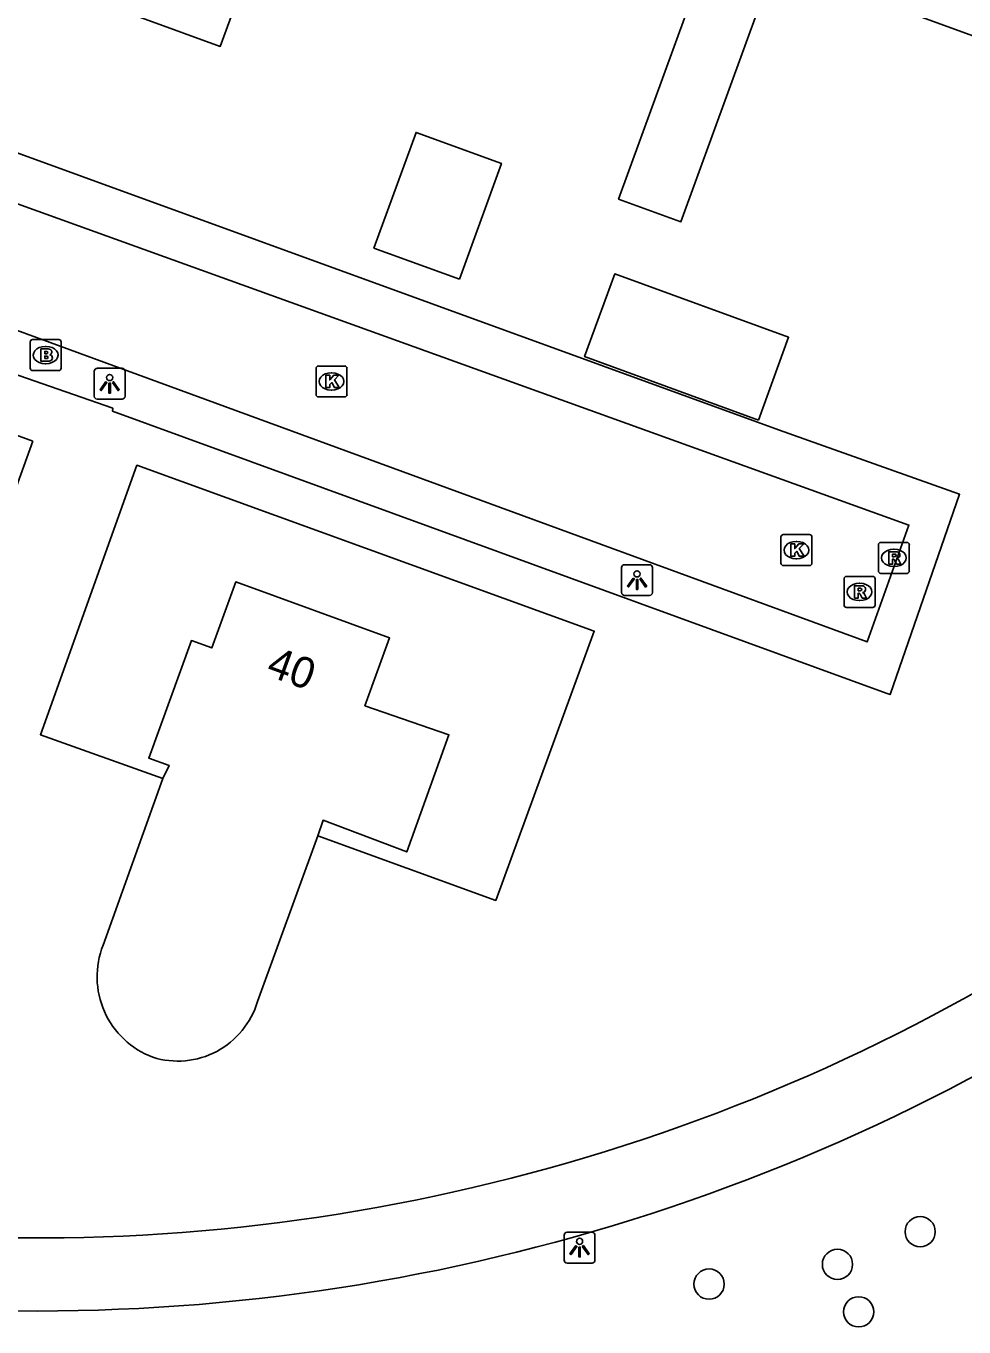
# Model space of a CAD drawing. Extents: x 155275 to 156263, y 382654 to 383635.
# Drawn here: x 155986.87 to 156017.19, y 382833.06 to 382875.11 of the extents above; entities that cross this region are included whole.
import ezdxf

# ---------------------------------------------------------------- set-up
doc = ezdxf.new("R2010")
doc.units = 0
for name, color, linetype in [('IMGEO_Boom', 7, 'Continuous'), ('IMGEO_Brandkraan', 7, 'Continuous'), ('IMGEO_Kolk', 7, 'Continuous'), ('IMGEO_Lichtpunt', 7, 'Continuous'), ('IMGEO_Pand', 7, 'Continuous'), ('IMGEO_Pand_nummerreeks', 7, 'Continuous'), ('IMGEO_Pand_overbouw', 7, 'Continuous'), ('IMGEO_Rijbaan_lokaal_open', 7, 'Continuous'), ('IMGEO_Rioolput', 7, 'Continuous'), ('IMGEO_Voetpad_open', 7, 'Continuous')]:
    doc.layers.add(name, color=color, linetype=linetype)

msp = doc.modelspace()

# ---------------------------------------------------------------- linework, layer by layer
at = {"layer": 'IMGEO_Boom'}
for centre in [(156015.775, 382836.141), (156013.102, 382835.085), (156008.951, 382834.447), (156013.787, 382833.551)]:
    msp.add_circle(centre, 0.489, dxfattribs=at)
at = {"layer": 'IMGEO_Brandkraan'}
for p, q in [((155987.002, 382864.048), (155987.002, 382864.9)), ((155987.077, 382864.974), (155987.929, 382864.974)), ((155988.003, 382864.9), (155988.003, 382864.048)), ((155987.49, 382864.754), (155987.515, 382864.754)), ((155987.929, 382863.974), (155987.077, 382863.974)), ((155987.513, 382864.194), (155987.488, 382864.194))]:
    msp.add_line(p, q, dxfattribs=at)
for points in [[(155987.002, 382864.048), (155987.002, 382864.9)], [(155987.077, 382864.974), (155987.929, 382864.974)], [(155988.003, 382864.9), (155988.003, 382864.048)], [(155987.35, 382864.674), (155987.35, 382864.274), (155987.563, 382864.274)], [(155987.581, 382864.674), (155987.35, 382864.674)], [(155987.529, 382864.593), (155987.475, 382864.593), (155987.475, 382864.517)], [(155987.475, 382864.517), (155987.528, 382864.517)], [(155987.537, 382864.441), (155987.475, 382864.441), (155987.475, 382864.36)], [(155987.475, 382864.36), (155987.537, 382864.36)], [(155987.929, 382863.974), (155987.077, 382863.974)]]:
    msp.add_lwpolyline(points, dxfattribs=at)
for centre, radius, start, end in [((155987.079, 382864.898), 0.0765, 91.552, 178.448), ((155987.079, 382864.898), 0.0765, 91.552, 178.448), ((155987.927, 382864.898), 0.0765, 1.552, 88.448), ((155987.927, 382864.898), 0.0765, 1.552, 88.448), ((155987.53, 382864.555), 0.0379, 267.8285, 90.9355), ((155987.538, 382864.4), 0.0404, 269.8759, 90.5077), ((155987.585, 382864.529), 0.145, 59.4692, 91.5367), ((155987.61, 382864.576), 0.0922, 285.5137, 58.1501), ((155987.615, 382864.384), 0.105, 301.3115, 78.989), ((155987.079, 382864.05), 0.0765, 181.552, 268.448), ((155987.079, 382864.05), 0.0765, 181.552, 268.448), ((155987.569, 382864.525), 0.251, 268.6676, 293.5347), ((155987.927, 382864.05), 0.0765, 271.552, 358.448), ((155987.927, 382864.05), 0.0765, 271.552, 358.448)]:
    msp.add_arc(centre, radius, start, end, dxfattribs=at)
for centre, major_axis, ratio, start_param, end_param in [((155987.489, 382864.474), (-0.387, 0.002), 0.722429, 4.712389, 7.853982), ((155987.514, 382864.474), (-0.39, 0.002), 0.717154, 1.570796, 4.712389)]:
    msp.add_ellipse(centre, major_axis=major_axis, ratio=ratio, start_param=start_param, end_param=end_param, dxfattribs=at)
at = {"layer": 'IMGEO_Kolk'}
for p, q in [((155996.244, 382863.195), (155996.244, 382864.047)), ((155996.319, 382864.121), (155997.171, 382864.121)), ((155997.245, 382864.047), (155997.245, 382863.195)), ((155996.732, 382863.901), (155996.757, 382863.901)), ((155997.171, 382863.121), (155996.319, 382863.121)), ((155996.755, 382863.341), (155996.73, 382863.341)), ((156011.275, 382857.745), (156011.275, 382858.597)), ((156011.35, 382858.671), (156012.202, 382858.671)), ((156012.276, 382858.597), (156012.276, 382857.745)), ((156011.763, 382858.451), (156011.788, 382858.451)), ((156012.202, 382857.671), (156011.35, 382857.671)), ((156011.786, 382857.891), (156011.761, 382857.891))]:
    msp.add_line(p, q, dxfattribs=at)
for points in [[(155996.244, 382863.195), (155996.244, 382864.047)], [(155996.319, 382864.121), (155997.171, 382864.121)], [(155997.245, 382864.047), (155997.245, 382863.195)], [(155996.565, 382863.821), (155996.688, 382863.821), (155996.688, 382863.67), (155996.818, 382863.821), (155996.982, 382863.821), (155996.836, 382863.67), (155996.989, 382863.421), (155996.837, 382863.421), (155996.752, 382863.585), (155996.688, 382863.518), (155996.688, 382863.421), (155996.565, 382863.421), (155996.565, 382863.821)], [(155997.171, 382863.121), (155996.319, 382863.121)], [(156011.275, 382857.745), (156011.275, 382858.597)], [(156011.35, 382858.671), (156012.202, 382858.671)], [(156012.276, 382858.597), (156012.276, 382857.745)], [(156011.596, 382858.371), (156011.719, 382858.371), (156011.719, 382858.22), (156011.849, 382858.371), (156012.013, 382858.371), (156011.867, 382858.22), (156012.02, 382857.971), (156011.868, 382857.971), (156011.783, 382858.135), (156011.719, 382858.068), (156011.719, 382857.971), (156011.596, 382857.971), (156011.596, 382858.371)], [(156012.202, 382857.671), (156011.35, 382857.671)]]:
    msp.add_lwpolyline(points, dxfattribs=at)
for centre, start, end in [((155996.321, 382864.045), 91.552, 178.448), ((155996.321, 382864.045), 91.552, 178.448), ((155997.169, 382864.045), 1.552, 88.448), ((155997.169, 382864.045), 1.552, 88.448), ((155996.321, 382863.197), 181.552, 268.448), ((155996.321, 382863.197), 181.552, 268.448), ((155997.169, 382863.197), 271.552, 358.448), ((155997.169, 382863.197), 271.552, 358.448), ((156011.352, 382858.595), 91.552, 178.448), ((156011.352, 382858.595), 91.552, 178.448), ((156012.2, 382858.595), 1.552, 88.448), ((156012.2, 382858.595), 1.552, 88.448), ((156011.352, 382857.747), 181.552, 268.448), ((156011.352, 382857.747), 181.552, 268.448), ((156012.2, 382857.747), 271.552, 358.448), ((156012.2, 382857.747), 271.552, 358.448)]:
    msp.add_arc(centre, 0.0765, start, end, dxfattribs=at)
for centre, major_axis, ratio, start_param, end_param in [((155996.731, 382863.621), (-0.387, 0.002), 0.722429, 4.712389, 7.853982), ((155996.756, 382863.621), (-0.39, 0.002), 0.717154, 1.570796, 4.712389), ((156011.762, 382858.171), (-0.387, 0.002), 0.722429, 4.712389, 7.853982), ((156011.787, 382858.171), (-0.39, 0.002), 0.717154, 1.570796, 4.712389)]:
    msp.add_ellipse(centre, major_axis=major_axis, ratio=ratio, start_param=start_param, end_param=end_param, dxfattribs=at)
at = {"layer": 'IMGEO_Lichtpunt'}
for p, q in [((155989.073, 382863.951), (155989.073, 382863.144)), ((155989.073, 382863.951), (155989.073, 382863.144)), ((155989.975, 382864.046), (155989.167, 382864.046)), ((155989.975, 382864.046), (155989.167, 382864.046)), ((155990.069, 382863.144), (155990.069, 382863.951)), ((155990.069, 382863.144), (155990.069, 382863.951)), ((155989.167, 382863.05), (155989.975, 382863.05)), ((155989.167, 382863.05), (155989.975, 382863.05)), ((156007.026, 382857.7), (156006.218, 382857.7)), ((156007.026, 382857.7), (156006.218, 382857.7)), ((156006.124, 382857.605), (156006.124, 382856.798)), ((156006.124, 382857.605), (156006.124, 382856.798)), ((156007.12, 382856.798), (156007.12, 382857.605)), ((156007.12, 382856.798), (156007.12, 382857.605)), ((156006.218, 382856.704), (156007.026, 382856.704)), ((156006.218, 382856.704), (156007.026, 382856.704)), ((156004.265, 382836.03), (156004.265, 382835.223)), ((156004.265, 382836.03), (156004.265, 382835.223)), ((156005.167, 382836.125), (156004.359, 382836.125)), ((156005.167, 382836.125), (156004.359, 382836.125)), ((156005.261, 382835.223), (156005.261, 382836.03)), ((156005.261, 382835.223), (156005.261, 382836.03)), ((156004.359, 382835.129), (156005.167, 382835.129)), ((156004.359, 382835.129), (156005.167, 382835.129))]:
    msp.add_line(p, q, dxfattribs=at)
for points in [[(155989.447, 382863.615), (155989.486, 382863.587), (155989.298, 382863.325), (155989.26, 382863.352), (155989.447, 382863.615)], [(155989.549, 382863.567), (155989.596, 382863.567), (155989.596, 382863.245), (155989.549, 382863.245), (155989.549, 382863.567)], [(155989.659, 382863.587), (155989.697, 382863.614), (155989.884, 382863.352), (155989.845, 382863.324), (155989.659, 382863.587)], [(156006.498, 382857.269), (156006.537, 382857.241), (156006.349, 382856.979), (156006.311, 382857.006), (156006.498, 382857.269)], [(156006.6, 382857.221), (156006.647, 382857.221), (156006.647, 382856.899), (156006.6, 382856.899), (156006.6, 382857.221)], [(156006.71, 382857.241), (156006.748, 382857.268), (156006.935, 382857.006), (156006.896, 382856.978), (156006.71, 382857.241)], [(156004.639, 382835.694), (156004.678, 382835.666), (156004.49, 382835.404), (156004.452, 382835.431), (156004.639, 382835.694)], [(156004.741, 382835.646), (156004.788, 382835.646), (156004.788, 382835.324), (156004.741, 382835.324), (156004.741, 382835.646)], [(156004.851, 382835.666), (156004.889, 382835.693), (156005.076, 382835.431), (156005.037, 382835.403), (156004.851, 382835.666)]]:
    msp.add_lwpolyline(points, dxfattribs=at)
for centre in [(155989.572, 382863.749), (156006.623, 382857.403), (156004.764, 382835.828)]:
    msp.add_circle(centre, 0.0994, dxfattribs=at)
for centre, start, end in [((155989.167, 382863.951), 90, 180), ((155989.167, 382863.951), 90, 180), ((155989.975, 382863.951), 0, 90), ((155989.975, 382863.951), 0, 90), ((155989.167, 382863.144), 180, 270), ((155989.167, 382863.144), 180, 270), ((155989.975, 382863.144), 270, 0), ((155989.975, 382863.144), 270, 360), ((156006.218, 382857.605), 90, 180), ((156006.218, 382857.605), 90, 180), ((156007.026, 382857.605), 0, 90), ((156007.026, 382857.605), 0, 90), ((156006.218, 382856.798), 180, 270), ((156006.218, 382856.798), 180, 270), ((156007.026, 382856.798), 270, 0), ((156007.026, 382856.798), 270, 360), ((156004.359, 382836.03), 90, 180), ((156004.359, 382836.03), 90, 180), ((156005.167, 382836.03), 0, 90), ((156005.167, 382836.03), 0, 90), ((156004.359, 382835.223), 180, 270), ((156004.359, 382835.223), 180, 270), ((156005.167, 382835.223), 270, 0), ((156005.167, 382835.223), 270, 360)]:
    msp.add_arc(centre, 0.0946, start, end, dxfattribs=at)
at = {"layer": 'IMGEO_Pand'}
for points in [[(156011.075, 382877.127), (156018.937, 382874.268), (156022.145, 382883.089), (156012.953, 382886.451), (156009.742, 382877.612), (156009.857, 382877.57)], [(155989.139, 382878.588), (155988.29, 382876.225), (155993.15, 382874.45), (155994.012, 382876.808), (155989.139, 382878.588)], [(156009.857, 382877.57), (156009.749, 382877.272), (156008.951, 382877.562), (156006.026, 382869.517), (156008.041, 382868.784), (156011.075, 382877.127)], [(156000.878, 382866.926), (155998.117, 382867.931), (155999.478, 382871.672), (156002.239, 382870.667), (156000.878, 382866.926)], [(156010.548, 382862.375), (156004.925, 382864.425), (156005.9, 382867.099), (156011.523, 382865.048), (156010.548, 382862.375)], [(155987.091, 382861.696), (155980.304, 382864.165), (155979.92, 382863.141), (155978.396, 382858.899), (155975.919, 382859.792), (155975.584, 382858.88), (155976.476, 382858.552), (155975.721, 382856.471), (155974.831, 382856.791), (155972.532, 382850.498), (155972.701, 382850.436), (155971.664, 382847.599), (155976.905, 382845.683), (155977.918, 382848.454), (155978.087, 382848.392), (155981.017, 382847.321), (155981.766, 382849.369), (155982.537, 382849.087), (155987.091, 382861.696)], [(155996.474, 382849.441), (155999.176, 382848.417), (156000.542, 382852.199), (155997.825, 382853.14), (155998.624, 382855.333), (155993.648, 382857.141), (155992.872, 382855.008), (155992.214, 382855.247), (155990.834, 382851.45), (155991.492, 382851.211), (155991.289, 382850.788), (155989.36, 382845.404)], [(155994.35, 382843.581), (155996.3, 382848.94), (155996.474, 382849.441)]]:
    msp.add_lwpolyline(points, dxfattribs=at)
for centre, radius, start, end in [((155991.945, 382844.381), 2.78, 158.4015, 249.3885), ((155991.773, 382844.341), 2.686, 252.5095, 343.5616)]:
    msp.add_arc(centre, radius, start, end, dxfattribs=at)
at = {"layer": 'IMGEO_Pand_overbouw'}
msp.add_lwpolyline([(155991.289, 382850.788), (155991.492, 382851.211), (155990.834, 382851.45), (155992.214, 382855.247), (155992.872, 382855.008), (155993.648, 382857.141), (155998.624, 382855.333), (155997.825, 382853.14), (156000.542, 382852.199), (155999.176, 382848.417), (155996.474, 382849.441), (155996.3, 382848.94), (156002.056, 382846.847), (156005.24, 382855.549), (155990.455, 382860.912), (155987.335, 382852.205)], close=True, dxfattribs=at)
at = {"layer": 'IMGEO_Rijbaan_lokaal_open'}
msp.add_lwpolyline([(155975.784, 382869.222), (156014.059, 382855.205), (156015.411, 382858.977), (155976.929, 382872.845)], dxfattribs=at)
at = {"layer": 'IMGEO_Rioolput'}
for p, q in [((156014.424, 382857.494), (156014.424, 382858.346)), ((156014.499, 382858.42), (156015.351, 382858.42)), ((156014.912, 382858.2), (156014.937, 382858.2)), ((156015.425, 382858.346), (156015.425, 382857.494)), ((156014.935, 382857.64), (156014.91, 382857.64)), ((156013.315, 382856.393), (156013.315, 382857.245)), ((156013.39, 382857.319), (156014.242, 382857.319)), ((156014.316, 382857.245), (156014.316, 382856.393)), ((156015.351, 382857.42), (156014.499, 382857.42)), ((156013.803, 382857.099), (156013.828, 382857.099)), ((156013.826, 382856.539), (156013.801, 382856.539)), ((156014.242, 382856.319), (156013.39, 382856.319))]:
    msp.add_line(p, q, dxfattribs=at)
for points in [[(156014.424, 382857.494), (156014.424, 382858.346)], [(156014.499, 382858.42), (156015.351, 382858.42)], [(156015.013, 382858.118), (156014.761, 382858.12), (156014.761, 382857.72)], [(156014.939, 382858.039), (156014.885, 382858.039), (156014.885, 382857.958)], [(156015.425, 382858.346), (156015.425, 382857.494)], [(156014.761, 382857.72), (156014.885, 382857.72), (156014.885, 382857.882), (156014.896, 382857.882)], [(156014.885, 382857.958), (156014.937, 382857.958)], [(156014.943, 382857.853), (156015.014, 382857.72), (156015.154, 382857.72), (156015.089, 382857.846)], [(156013.315, 382856.393), (156013.315, 382857.245)], [(156013.39, 382857.319), (156014.242, 382857.319)], [(156014.316, 382857.245), (156014.316, 382856.393)], [(156015.351, 382857.42), (156014.499, 382857.42)], [(156013.904, 382857.017), (156013.652, 382857.019), (156013.652, 382856.619)], [(156013.652, 382856.619), (156013.776, 382856.619), (156013.776, 382856.781), (156013.787, 382856.781)], [(156013.83, 382856.938), (156013.776, 382856.938), (156013.776, 382856.857)], [(156013.776, 382856.857), (156013.828, 382856.857)], [(156013.834, 382856.752), (156013.905, 382856.619), (156014.045, 382856.619), (156013.98, 382856.745)], [(156014.242, 382856.319), (156013.39, 382856.319)]]:
    msp.add_lwpolyline(points, dxfattribs=at)
for centre, radius, start, end in [((156014.501, 382858.344), 0.0765, 91.552, 178.448), ((156014.501, 382858.344), 0.0765, 91.552, 178.448), ((156014.945, 382857.943), 0.0964, 77.0061, 93.1865), ((156015.012, 382858.008), 0.109, 350.3612, 89.416), ((156015.349, 382858.344), 0.0765, 1.552, 88.448), ((156015.349, 382858.344), 0.0765, 1.552, 88.448), ((156014.895, 382857.829), 0.0533, 26.0293, 88.6989), ((156014.921, 382858.147), 0.19, 274.7715, 282.9687), ((156014.959, 382858), 0.0378, 276.6634, 79.6772), ((156015.01, 382858.008), 0.112, 277.5842, 350.9817), ((156014.994, 382857.793), 0.108, 29.5134, 73.7905), ((156013.392, 382857.243), 0.0765, 91.552, 178.448), ((156013.392, 382857.243), 0.0765, 91.552, 178.448), ((156014.24, 382857.243), 0.0765, 1.552, 88.448), ((156014.24, 382857.243), 0.0765, 1.552, 88.448), ((156014.501, 382857.496), 0.0765, 181.552, 268.448), ((156014.501, 382857.496), 0.0765, 181.552, 268.448), ((156015.349, 382857.496), 0.0765, 271.552, 358.448), ((156015.349, 382857.496), 0.0765, 271.552, 358.448), ((156013.786, 382856.728), 0.0533, 26.0293, 88.6989), ((156013.812, 382857.046), 0.19, 274.7715, 282.9687), ((156013.836, 382856.842), 0.0964, 77.0061, 93.1865), ((156013.85, 382856.899), 0.0378, 276.6634, 79.6772), ((156013.903, 382856.907), 0.109, 350.3612, 89.416), ((156013.901, 382856.907), 0.112, 277.5842, 350.9817), ((156013.885, 382856.692), 0.108, 29.5134, 73.7905), ((156013.392, 382856.395), 0.0765, 181.552, 268.448), ((156013.392, 382856.395), 0.0765, 181.552, 268.448), ((156014.24, 382856.395), 0.0765, 271.552, 358.448), ((156014.24, 382856.395), 0.0765, 271.552, 358.448)]:
    msp.add_arc(centre, radius, start, end, dxfattribs=at)
for centre, major_axis, ratio, start_param, end_param in [((156014.911, 382857.92), (-0.387, 0.002), 0.722429, 4.712389, 7.853982), ((156014.936, 382857.92), (-0.39, 0.002), 0.717154, 1.570796, 4.712389), ((156013.802, 382856.819), (-0.387, 0.002), 0.722429, 4.712389, 7.853982), ((156013.827, 382856.819), (-0.39, 0.002), 0.717154, 1.570796, 4.712389)]:
    msp.add_ellipse(centre, major_axis=major_axis, ratio=ratio, start_param=start_param, end_param=end_param, dxfattribs=at)
at = {"layer": 'IMGEO_Voetpad_open'}
msp.add_lwpolyline([(155975.249, 382867.763), (155989.671, 382862.757), (155989.659, 382862.664), (156014.672, 382853.55), (156014.804, 382853.502), (156017.047, 382859.976), (156011.194, 382862.059), (155977.474, 382874.314)], dxfattribs=at)
for centre, radius, start, end in [((155987.192, 382897.947), 62.009, 263.74156, 301.41848), ((155987.19, 382897.956), 64.379, 264.20988, 301.40199)]:
    msp.add_arc(centre, radius, start, end, dxfattribs=at)

# ---------------------------------------------------------------- texts
at = {"layer": 'IMGEO_Pand_nummerreeks'}
msp.add_text('40', height=1, rotation=340.0317, dxfattribs=at).set_placement((155994.592, 382854.138))

doc.saveas('drawing.dxf')
